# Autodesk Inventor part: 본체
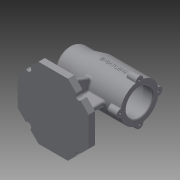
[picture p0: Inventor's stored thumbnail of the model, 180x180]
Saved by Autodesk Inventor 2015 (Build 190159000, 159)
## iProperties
Created: 2019-12
Part Number: 본체
Material: 일반
Document SubType Name: Modeling
Designer: CAD-08
Density: 1 g/cm^3
Appearance: 기본값
Author: CAD-08
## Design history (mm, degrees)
sketch "스케치1" dims "d0" = 112
  geometry: L1 (0, -56)-(-39.598, -39.598); L2 (-39.598, -39.598)-(-56, 0); L3 (-56, 0)-(-39.598, 39.598); L4 (-39.598, 39.598)-(0, 56); L5 (0, 56)-(39.598, 39.598); L6 (39.598, 39.598)-(56, 0); L7 (56, 0)-(39.598, -39.598); L8 (39.598, -39.598)-(0, -56); L9 (-23.196, -56)-(-56, -23.196); L10 (-56, -23.196)-(-56, 23.196); L11 (-56, 23.196)-(-23.196, 56); L12 (-23.196, 56)-(23.196, 56); L13 (23.196, 56)-(56, 23.196); L14 (56, 23.196)-(56, -23.196); L15 (56, -23.196)-(23.196, -56); L16 (23.196, -56)-(-23.196, -56); 4 further points
  constraints: 32 end point, 3 coincident, 1 horizontal alignment, 1 midpoint, 1 vertical alignment, 36 other
extrude "돌출1" new body sketch "스케치1" distance "d1" = 10; taper "d2" = 0 deg
sketch "스케치2"
  geometry: L1 (56, 23.196)-(23.196, 56) reference; L2 (-23.196, 56)-(-56, 23.196) reference; L3 (0, 0)-(-27.881, 0); L4 (-27.881, 0)-(0, 0); L5 (0, 30.128)-(0, 0); L6 (0, 0)-(-39.598, 39.598); C1 r 5 at (-39.598, 39.598); C2 r 5 at (39.598, 39.598); C3 r 5 at (-39.598, -39.598); C4 r 5 at (39.598, -39.598)
  constraints: 8 end point, 4 centre point, 2 midpoint, 2 symmetric about line, 1 collinear, 1 horizontal, 1 perpendicular, 2 other
  dimensions: "d3" = 10 diameter of C2; "d4" = 10 diameter of C1
extrude "돌출2" cut sketch "스케치2" distance "d5" = 10; taper "d6" = 0 deg
sketch "스케치3"
  geometry: L1 (56, -23.196)-(56, 23.196) reference; L2 (23.196, 56)-(-23.196, 56) reference; L3 (-56, 23.196)-(-56, -23.196) reference; L4 (-23.196, -56)-(23.196, -56) reference; L5 (-38, 4)-(31, 4); L6 (31, 4)-(31, -4); L7 (31, -4)-(-38, -4); L8 (-38, -4)-(-38, 4); L9 (4, -36)-(-4, -36); L10 (-4, -36)-(-4, 36); L11 (-4, 36)-(4, 36); L12 (4, 36)-(4, -36); 1 further point
  constraints: 16 end point, 4 parallel, 2 horizontal, 2 perpendicular
  dimensions: "d7" = 8 distance of L10.end L11.end; "d8" = 8 distance of L5.end L6.end; "d9" = 18 distance between parallel lines of L8 L3; "d10" = 25 distance between parallel lines of L1 L6; "d11" = 20 distance between parallel lines of L2 L11; "d12" = 20 distance between parallel lines of L4 L9; "d13" = 4 distance from line of point (0, 0) L10; "d14" = 4 distance from line of point (0, 0) L5
extrude "돌출3" join sketch "스케치3" distance "d15" = 70; taper "d16" = 0 deg
feature "면 기울기1" dims angle "d17" = 25 deg
feature "면 기울기2" dims angle "d18" = 20 deg
sketch "스케치4"
  geometry: L1 (56, 0)-(-56, 0) reference; L2 (-56, 0)-(-56, 10) reference; L3 (-56, 10)-(-38, 10) reference; L4 (-38, 10)-(-5.358, 80) reference; L5 (-5.358, 80)-(31, 80) reference; L6 (31, 80)-(31, 10) reference; L7 (31, 10)-(56, 10) reference; L8 (56, 10)-(56, 0) reference; L9 (-11, 110)-(56, 110); L10 (56, 110)-(56, 80); L11 (56, 80)-(-56, 80); L12 (-56, 80)-(-56, 105); L13 (-56, 105)-(-31, 105); L14 (-31, 105)-(-11, 110); 1 further point
  constraints: 12 end point, 2 collinear, 2 horizontal, 2 parallel, 1 perpendicular
  dimensions: "d20" = 112 distance between parallel lines of L10 L12; "d21" = 45 distance from line of L12 L9.start; "d22" = 25 distance of L12.end L13.end; "d23" = 30 distance between parallel lines of L11 L9; "d24" = 25 distance between parallel lines of L11 L13
revolve "회전1" sketch "스케치4" stored, may be unused: angle "d25" = 90 deg
sketch "스케치5"
  geometry: C1 r 30 at (0, 0) reference; 1 further point
hole "구멍1" sketch "스케치5" at (0, 0) diameter "d26" = 42; stored, may be unused: countersink angle "d30" = 90 deg, drill point angle "d32" = 0 deg; dims "d27" = 6, "d28" = 4, "d29" = 2, "d31" = 15
sketch "스케치6"
  geometry: C1 r 21 at (0, 0) reference; 1 further point
hole "구멍2" sketch "스케치6" at (0, 0) diameter "d33" = 48; stored, may be unused: countersink angle "d37" = 90 deg, drill point angle "d39" = 0 deg; dims "d34" = 6, "d35" = 4, "d36" = 2, "d38" = 54
sketch "스케치7"
  geometry: C1 r 24 at (0, 0) reference; 1 further point
hole "구멍3" sketch "스케치7" at (0, 0) diameter "d40" = 42; stored, may be unused: countersink angle "d44" = 90 deg, drill point angle "d46" = 0 deg; dims "d41" = 6, "d42" = 4, "d43" = 2, "d45" = 12
sketch "스케치8"
  geometry: C1 r 21 at (0, 0) reference; 1 further point
hole "구멍4" sketch "스케치8" at (0, 0) diameter "d47" = 35; stored, may be unused: countersink angle "d51" = 90 deg, drill point angle "d53" = 0 deg; dims "d48" = 6, "d49" = 4, "d50" = 2, "d52" = 18
sketch "스케치9"
  geometry: C1 r 17.5 at (0, 0) reference; 1 further point
hole "구멍5" sketch "스케치9" at (0, 0) diameter "d54" = 32; stored, may be unused: countersink angle "d58" = 90 deg, drill point angle "d60" = 0 deg; dims "d55" = 6, "d56" = 4, "d57" = 2, "d59" = 4
sketch "스케치10"
  geometry: C1 r 16 at (0, 0) reference; 1 further point
hole "구멍6" sketch "스케치10" at (0, 0) diameter "d61" = 21; stored, may be unused: countersink angle "d65" = 90 deg, drill point angle "d67" = 0 deg; dims "d62" = 6, "d63" = 4, "d64" = 2, "d66" = 3
sketch "스케치11"
  geometry: C1 r 21 at (0, 0) reference; C2 r 6 at (0, 30); 2 further points
  constraints: 2 vertical alignment, 1 centre point, 1 other
  dimensions: "d68" = 12 diameter of C2
extrude "돌출4" join sketch "스케치11" distance "d69" = 16; taper "d70" = 0 deg
sketch "스케치12"
  geometry: A1 r 6 centre (0, 0) between (5.97, -0.6) and (-5.97, -0.6) reference; 1 further point
hole "구멍7" sketch "스케치12" at (0, 0) diameter "d71" = 3.242; stored, may be unused: countersink angle "d75" = 90 deg, drill point angle "d77" = 118 deg; dims "d72" = 8, "d73" = 4, "d74" = 2, "d76" = 11
fillet "모깎기1" dims "d78" = 10
fillet "모깎기2" dims "d79" = 3
fillet "모깎기3" dims "d80" = 1
fillet "모깎기4" dims "d84" = 0.3
fillet "모깎기5" dims "d85" = 3
chamfer "모따기1" distance "d86" = 1; stored, may be unused: second distance "d87" = 2, angle "d88" = 45 deg
fillet "모깎기6" dims "d89" = 3
fillet "모깎기7" dims "d90" = 3
fillet "모깎기8" dims "d91" = 3
fillet "모깎기9" dims "d92" = 3
node "작업 평면1"
sketch "스케치13"
  geometry: L1 (33.5, 36)-(33.5, 30.171) reference; L2 (-33.131, 30)-(16.5, 30) reference; 2 further points
  constraints: 1 other
  dimensions: "d93" = 41 distance from line of L1 point (-7.5, 0); "d94" = 30 distance from line of L2 point (-7.5, 0)
feature "엠보싱1" sketch "스케치13" dims "d95" = 0.5, "d96" = 0
fillet "모깎기10" dims "d97" = 3
node "솔리드1"
pattern_circular "원형 패턴1" dims "d82" = 360 deg
node "절단 모서리 투영1"
